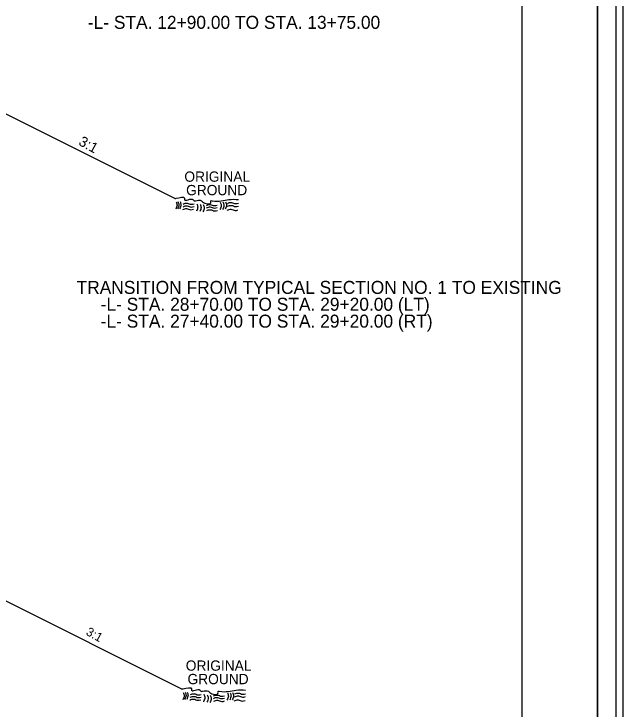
# Model space of a CAD drawing. Extents: x 1593595 to 1594166, y 741647 to 741854.
# Drawn here: x 1594092.9 to 1594141.4, y 741724.8 to 741780.2 of the extents above; entities that cross this region are included whole.
import ezdxf

# ---------------------------------------------------------------- set-up
doc = ezdxf.new("R2010")
doc.units = 0
for name, color, linetype in [('Old_Level_1', 7, 'Continuous'), ('Old_Level_2', 7, 'Continuous'), ('Prop Dimension', 7, 'Continuous'), ('Sheet Clip Boundary CELL', 7, 'Continuous'), ('Sheet Layout Plan Border', 7, 'Continuous'), ('Sheet Plan CELL', 7, 'Continuous'), ('Sheet Plan Layout CELL', 7, 'Continuous'), ('Sheet Plot Border Inside CELL', 7, 'Continuous'), ('Sheet Plot Border Outside CELL', 7, 'Continuous'), ('Typical Text General CELL', 7, 'Continuous')]:
    doc.layers.add(name, color=color, linetype=linetype)

msp = doc.modelspace()

# ---------------------------------------------------------------- linework, layer by layer
at = {"layer": 'Old_Level_1'}
for p, q in [((1594105.684, 741765.469), (1594090.919, 741772.851)), ((1594106.247, 741726.422), (1594091.483, 741733.805))]:
    msp.add_line(p, q, dxfattribs=at)
at = {"layer": 'Old_Level_2'}
for points in [[(1594105.684, 741765.469), (1594105.797, 741765.481), (1594106.465, 741765.481), (1594106.465, 741765.386), (1594107.134, 741765.386), (1594107.229, 741765.29), (1594107.324, 741765.29), (1594107.802, 741765.29), (1594107.897, 741765.195), (1594108.565, 741765.195), (1594108.565, 741765.29), (1594108.661, 741765.29), (1594109.997, 741765.386), (1594110.758, 741765.386)], [(1594105.792, 741765.2), (1594105.867, 741764.944), (1594105.76, 741764.612)], [(1594105.942, 741765.222), (1594106.016, 741764.965), (1594105.909, 741764.633)], [(1594106.102, 741765.232), (1594106.177, 741764.976), (1594106.07, 741764.644)], [(1594106.364, 741765.024), (1594106.674, 741765.099), (1594106.995, 741765.002), (1594107.23, 741765.045)], [(1594109.309, 741765.168), (1594109.384, 741764.911), (1594109.277, 741764.58)], [(1594109.523, 741765.179), (1594109.598, 741764.922), (1594109.491, 741764.591)], [(1594109.726, 741765.2), (1594109.801, 741764.944), (1594109.694, 741764.612)], [(1594109.892, 741765.077), (1594110.202, 741765.152), (1594110.523, 741765.056), (1594110.758, 741765.099)], [(1594106.321, 741764.596), (1594106.631, 741764.671), (1594106.952, 741764.575), (1594107.187, 741764.617)], [(1594106.353, 741764.81), (1594106.663, 741764.885), (1594106.984, 741764.788), (1594107.219, 741764.831)], [(1594107.438, 741765.05), (1594107.513, 741764.794), (1594107.406, 741764.462)], [(1594107.706, 741765.018), (1594107.78, 741764.762), (1594107.673, 741764.43)], [(1594107.951, 741764.986), (1594108.026, 741764.73), (1594107.919, 741764.398)], [(1594108.203, 741764.917), (1594108.513, 741764.992), (1594108.833, 741764.895), (1594109.069, 741764.938)], [(1594108.203, 741764.724), (1594108.513, 741764.799), (1594108.833, 741764.703), (1594109.069, 741764.746)], [(1594108.224, 741764.5), (1594108.534, 741764.575), (1594108.855, 741764.478), (1594109.09, 741764.521)], [(1594109.849, 741764.532), (1594110.159, 741764.607), (1594110.48, 741764.51), (1594110.715, 741764.553)], [(1594109.881, 741764.842), (1594110.191, 741764.917), (1594110.512, 741764.821), (1594110.747, 741764.863)], [(1594106.247, 741726.422), (1594106.361, 741726.435), (1594107.029, 741726.435), (1594107.029, 741726.339), (1594107.697, 741726.339), (1594107.793, 741726.244), (1594107.888, 741726.244), (1594108.365, 741726.244), (1594108.461, 741726.148), (1594109.129, 741726.148), (1594109.129, 741726.244), (1594109.224, 741726.244), (1594110.561, 741726.339), (1594111.321, 741726.339)], [(1594106.355, 741726.154), (1594106.43, 741725.897), (1594106.323, 741725.566)], [(1594106.505, 741726.175), (1594106.58, 741725.918), (1594106.473, 741725.587)], [(1594106.665, 741726.186), (1594106.74, 741725.929), (1594106.633, 741725.598)], [(1594106.917, 741725.763), (1594107.227, 741725.838), (1594107.548, 741725.742), (1594107.783, 741725.785)], [(1594106.927, 741725.977), (1594107.237, 741726.052), (1594107.558, 741725.956), (1594107.793, 741725.999)], [(1594108.002, 741726.004), (1594108.077, 741725.747), (1594107.97, 741725.416)], [(1594108.269, 741725.972), (1594108.344, 741725.715), (1594108.237, 741725.384)], [(1594108.515, 741725.94), (1594108.59, 741725.683), (1594108.483, 741725.352)], [(1594108.766, 741725.87), (1594109.076, 741725.945), (1594109.397, 741725.849), (1594109.632, 741725.892)], [(1594109.873, 741726.122), (1594109.948, 741725.865), (1594109.841, 741725.533)], [(1594110.087, 741726.132), (1594110.161, 741725.876), (1594110.054, 741725.544)], [(1594110.29, 741726.154), (1594110.364, 741725.897), (1594110.258, 741725.566)], [(1594110.445, 741725.795), (1594110.755, 741725.87), (1594111.076, 741725.774), (1594111.311, 741725.817)], [(1594110.456, 741726.031), (1594110.766, 741726.105), (1594111.086, 741726.009), (1594111.321, 741726.052)], [(1594106.885, 741725.549), (1594107.195, 741725.624), (1594107.515, 741725.528), (1594107.751, 741725.571)], [(1594108.766, 741725.678), (1594109.076, 741725.753), (1594109.397, 741725.656), (1594109.632, 741725.699)], [(1594108.788, 741725.453), (1594109.098, 741725.528), (1594109.418, 741725.432), (1594109.654, 741725.475)], [(1594110.413, 741725.485), (1594110.723, 741725.56), (1594111.043, 741725.464), (1594111.279, 741725.507)]]:
    msp.add_spline(points, degree=3, dxfattribs=at)
at = {"layer": 'Sheet Clip Boundary CELL'}
msp.add_lwpolyline([(1593965.316, 741705.56), (1594133.318, 741705.56), (1594133.318, 741806.182), (1594110.606, 741806.182), (1594110.606, 741831.56), (1593965.316, 741831.56)], close=True, dxfattribs=at)
at = {"layer": 'Sheet Layout Plan Border'}
msp.add_lwpolyline([(1593965.316, 741705.56), (1594133.318, 741705.56), (1594133.318, 741806.182), (1594110.606, 741806.182), (1594110.606, 741831.56), (1593965.316, 741831.56)], close=True, dxfattribs=at)
at = {"layer": 'Sheet Plan CELL'}
for points in [[(1593959.316, 741705.56), (1593959.313, 741831.557), (1594115.312, 741831.562), (1594115.313, 741813.554), (1594139.318, 741813.553), (1594139.318, 741705.56)], [(1594139.321, 741831.56), (1593959.316, 741831.56), (1593959.316, 741705.56), (1594139.318, 741705.56)]]:
    msp.add_lwpolyline(points, close=True, dxfattribs=at)
at = {"layer": 'Sheet Plan Layout CELL'}
msp.add_lwpolyline([(1593959.313, 741831.557), (1593959.316, 741705.56), (1594139.316, 741705.56), (1594139.316, 741806.182), (1594110.606, 741806.182), (1594110.606, 741831.56)], close=True, dxfattribs=at)
at = {"layer": 'Sheet Plot Border Inside CELL'}
msp.add_lwpolyline([(1593940.898, 741705.259), (1594140.816, 741705.26), (1594140.818, 741831.859), (1593940.898, 741831.859)], close=True, dxfattribs=at)
at = {"layer": 'Sheet Plot Border Outside CELL'}
msp.add_lwpolyline([(1593939.338, 741702.859), (1594141.358, 741702.859), (1594141.358, 741834.259), (1593939.338, 741834.259)], close=True, dxfattribs=at)

# ---------------------------------------------------------------- texts
at = {"layer": 'Old_Level_1'}
for s, p in [('ORIGINAL', (1594106.45, 741766.798)), ('GROUND', (1594106.588, 741765.726)), ('ORIGINAL', (1594106.562, 741727.88)), ('GROUND', (1594106.7, 741726.808))]:
    msp.add_text(s, height=0.8181, dxfattribs=at).set_placement(p)
at = {"layer": 'Prop Dimension'}
for s, p in [('     -L- STA. 12+90.00 TO STA. 13+75.00', (1594096.847, 741778.969)), ('TRANSITION FROM TYPICAL SECTION NO. 1 TO EXISTING', (1594097.871, 741757.873)), ('     -L- STA. 28+70.00 TO STA. 29+20.00 (LT)', (1594097.871, 741756.53)), ('     -L- STA. 27+40.00 TO STA. 29+20.00 (RT)', (1594097.871, 741755.187))]:
    msp.add_text(s, height=1.03302, dxfattribs=at).set_placement(p)
at = {"layer": 'Typical Text General CELL'}
for height, p in [(0.8181, (1594097.968, 741769.767)), (0.7025, (1594098.559, 741730.771))]:
    msp.add_text('3:1', height=height, rotation=331.0265, dxfattribs=at).set_placement(p)

doc.saveas('drawing.dxf')
